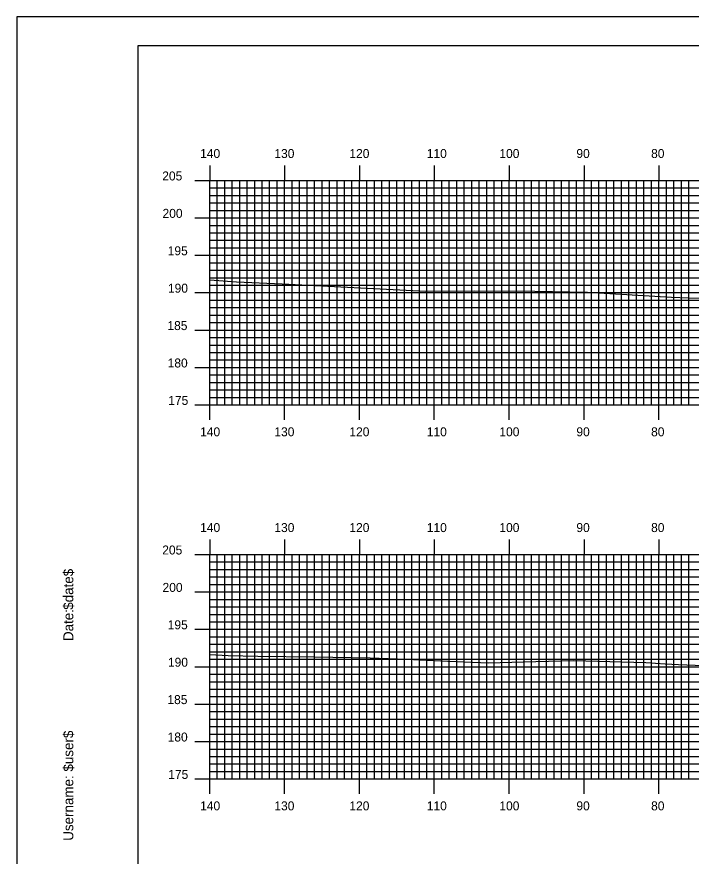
# Model space of a CAD drawing. Extents: x 1807832 to 1808175, y 442591 to 442811.
# Drawn here: x 1807832 to 1807922.1, y 442698.3 to 442810.5 of the extents above; entities that cross this region are included whole.
import ezdxf

# ---------------------------------------------------------------- set-up
doc = ezdxf.new("R2010")
doc.units = 0
for name, color, linetype in [('BORDER', 7, 'Continuous'), ('H_V ANNOTATION', 7, 'Continuous'), ('MAJOR', 7, 'Continuous'), ('MINOR', 7, 'Continuous'), ('PLOT BOUNDARY', 7, 'Continuous'), ('S_Roadway_Centerline', 7, 'Continuous')]:
    doc.layers.add(name, color=color, linetype=linetype)

msp = doc.modelspace()

# ---------------------------------------------------------------- linework, layer by layer
at = {"layer": 'BORDER'}
msp.add_lwpolyline([(1807848.18, 442596.67), (1808168.18, 442596.67), (1808168.18, 442806.67), (1807848.18, 442806.67)], close=True, dxfattribs=at)
at = {"layer": 'MAJOR'}
for p, q in [((1807857.78, 442790.67), (1807857.78, 442788.67)), ((1807867.78, 442790.67), (1807867.78, 442788.67)), ((1807877.78, 442790.67), (1807877.78, 442788.67)), ((1807887.78, 442790.67), (1807887.78, 442788.67)), ((1807897.78, 442790.67), (1807897.78, 442788.67)), ((1807907.78, 442790.67), (1807907.78, 442788.67)), ((1807917.78, 442790.67), (1807917.78, 442788.67)), ((1807855.78, 442788.67), (1807857.78, 442788.67)), ((1807857.78, 442788.67), (1808137.78, 442788.67)), ((1807857.78, 442758.67), (1807857.78, 442788.67)), ((1807857.78, 442758.67), (1807857.78, 442788.67)), ((1807857.78, 442788.67), (1808137.78, 442788.67)), ((1807867.78, 442758.67), (1807867.78, 442788.67)), ((1807877.78, 442758.67), (1807877.78, 442788.67)), ((1807887.78, 442758.67), (1807887.78, 442788.67)), ((1807897.78, 442758.67), (1807897.78, 442788.67)), ((1807907.78, 442758.67), (1807907.78, 442788.67)), ((1807917.78, 442758.67), (1807917.78, 442788.67)), ((1807855.78, 442783.67), (1807857.78, 442783.67)), ((1807857.78, 442783.67), (1808137.78, 442783.67)), ((1807855.78, 442778.67), (1807857.78, 442778.67)), ((1807857.78, 442778.67), (1808137.78, 442778.67)), ((1807855.78, 442773.67), (1807857.78, 442773.67)), ((1807857.78, 442773.67), (1808137.78, 442773.67)), ((1807855.78, 442768.67), (1807857.78, 442768.67)), ((1807857.78, 442768.67), (1808137.78, 442768.67)), ((1807855.78, 442763.67), (1807857.78, 442763.67)), ((1807857.78, 442763.67), (1808137.78, 442763.67)), ((1807855.78, 442758.67), (1807857.78, 442758.67)), ((1807857.78, 442758.67), (1808137.78, 442758.67)), ((1807857.78, 442758.67), (1808137.78, 442758.67)), ((1807857.78, 442756.66), (1807857.78, 442758.67)), ((1807867.78, 442756.66), (1807867.78, 442758.67)), ((1807877.78, 442756.66), (1807877.78, 442758.67)), ((1807887.78, 442756.66), (1807887.78, 442758.67)), ((1807897.78, 442756.66), (1807897.78, 442758.67)), ((1807907.78, 442756.66), (1807907.78, 442758.67)), ((1807917.78, 442756.66), (1807917.78, 442758.67)), ((1807857.78, 442740.67), (1807857.78, 442738.67)), ((1807867.78, 442740.67), (1807867.78, 442738.67)), ((1807877.78, 442740.67), (1807877.78, 442738.67)), ((1807887.78, 442740.67), (1807887.78, 442738.67)), ((1807897.78, 442740.67), (1807897.78, 442738.67)), ((1807907.78, 442740.67), (1807907.78, 442738.67)), ((1807917.78, 442740.67), (1807917.78, 442738.67)), ((1807855.78, 442738.67), (1807857.78, 442738.67)), ((1807857.78, 442738.67), (1808137.78, 442738.67)), ((1807857.78, 442708.67), (1807857.78, 442738.67)), ((1807857.78, 442708.67), (1807857.78, 442738.67)), ((1807857.78, 442738.67), (1808137.78, 442738.67)), ((1807867.78, 442708.67), (1807867.78, 442738.67)), ((1807877.78, 442708.67), (1807877.78, 442738.67)), ((1807887.78, 442708.67), (1807887.78, 442738.67)), ((1807897.78, 442708.67), (1807897.78, 442738.67)), ((1807907.78, 442708.67), (1807907.78, 442738.67)), ((1807917.78, 442708.67), (1807917.78, 442738.67)), ((1807855.78, 442733.67), (1807857.78, 442733.67)), ((1807857.78, 442733.67), (1808137.78, 442733.67)), ((1807855.78, 442728.67), (1807857.78, 442728.67)), ((1807857.78, 442728.67), (1808137.78, 442728.67)), ((1807855.78, 442723.67), (1807857.78, 442723.67)), ((1807857.78, 442723.67), (1808137.78, 442723.67)), ((1807855.78, 442718.67), (1807857.78, 442718.67)), ((1807857.78, 442718.67), (1808137.78, 442718.67)), ((1807855.78, 442713.67), (1807857.78, 442713.67)), ((1807857.78, 442713.67), (1808137.78, 442713.67)), ((1807855.78, 442708.67), (1807857.78, 442708.67)), ((1807857.78, 442708.67), (1808137.78, 442708.67)), ((1807857.78, 442708.67), (1808137.78, 442708.67)), ((1807857.78, 442706.66), (1807857.78, 442708.67)), ((1807867.78, 442706.66), (1807867.78, 442708.67)), ((1807877.78, 442706.66), (1807877.78, 442708.67)), ((1807887.78, 442706.66), (1807887.78, 442708.67)), ((1807897.78, 442706.66), (1807897.78, 442708.67)), ((1807907.78, 442706.66), (1807907.78, 442708.67)), ((1807917.78, 442706.66), (1807917.78, 442708.67))]:
    msp.add_line(p, q, dxfattribs=at)
at = {"layer": 'MINOR'}
for p, q in [((1807858.78, 442758.67), (1807858.78, 442788.67)), ((1807859.78, 442758.67), (1807859.78, 442788.67)), ((1807860.78, 442758.67), (1807860.78, 442788.67)), ((1807861.78, 442758.67), (1807861.78, 442788.67)), ((1807862.78, 442758.67), (1807862.78, 442788.67)), ((1807863.78, 442758.67), (1807863.78, 442788.67)), ((1807864.78, 442758.67), (1807864.78, 442788.67)), ((1807865.78, 442758.67), (1807865.78, 442788.67)), ((1807866.78, 442758.67), (1807866.78, 442788.67)), ((1807868.78, 442758.67), (1807868.78, 442788.67)), ((1807869.78, 442758.67), (1807869.78, 442788.67)), ((1807870.78, 442758.67), (1807870.78, 442788.67)), ((1807871.78, 442758.67), (1807871.78, 442788.67)), ((1807872.78, 442758.67), (1807872.78, 442788.67)), ((1807873.78, 442758.67), (1807873.78, 442788.67)), ((1807874.78, 442758.67), (1807874.78, 442788.67)), ((1807875.78, 442758.67), (1807875.78, 442788.67)), ((1807876.78, 442758.67), (1807876.78, 442788.67)), ((1807878.78, 442758.67), (1807878.78, 442788.67)), ((1807879.78, 442758.67), (1807879.78, 442788.67)), ((1807880.78, 442758.67), (1807880.78, 442788.67)), ((1807881.78, 442758.67), (1807881.78, 442788.67)), ((1807882.78, 442758.67), (1807882.78, 442788.67)), ((1807883.78, 442758.67), (1807883.78, 442788.67)), ((1807884.78, 442758.67), (1807884.78, 442788.67)), ((1807885.78, 442758.67), (1807885.78, 442788.67)), ((1807886.78, 442758.67), (1807886.78, 442788.67)), ((1807888.78, 442758.67), (1807888.78, 442788.67)), ((1807889.78, 442758.67), (1807889.78, 442788.67)), ((1807890.78, 442758.67), (1807890.78, 442788.67)), ((1807891.78, 442758.67), (1807891.78, 442788.67)), ((1807892.78, 442758.67), (1807892.78, 442788.67)), ((1807893.78, 442758.67), (1807893.78, 442788.67)), ((1807894.78, 442758.67), (1807894.78, 442788.67)), ((1807895.78, 442758.67), (1807895.78, 442788.67)), ((1807896.78, 442758.67), (1807896.78, 442788.67)), ((1807898.78, 442758.67), (1807898.78, 442788.67)), ((1807899.78, 442758.67), (1807899.78, 442788.67)), ((1807900.78, 442758.67), (1807900.78, 442788.67)), ((1807901.78, 442758.67), (1807901.78, 442788.67)), ((1807902.78, 442758.67), (1807902.78, 442788.67)), ((1807903.78, 442758.67), (1807903.78, 442788.67)), ((1807904.78, 442758.67), (1807904.78, 442788.67)), ((1807905.78, 442758.67), (1807905.78, 442788.67)), ((1807906.78, 442758.67), (1807906.78, 442788.67)), ((1807908.78, 442758.67), (1807908.78, 442788.67)), ((1807909.78, 442758.67), (1807909.78, 442788.67)), ((1807910.78, 442758.67), (1807910.78, 442788.67)), ((1807911.78, 442758.67), (1807911.78, 442788.67)), ((1807912.78, 442758.67), (1807912.78, 442788.67)), ((1807913.78, 442758.67), (1807913.78, 442788.67)), ((1807914.78, 442758.67), (1807914.78, 442788.67)), ((1807915.78, 442758.67), (1807915.78, 442788.67)), ((1807916.78, 442758.67), (1807916.78, 442788.67)), ((1807918.78, 442758.67), (1807918.78, 442788.67)), ((1807919.78, 442758.67), (1807919.78, 442788.67)), ((1807920.78, 442758.67), (1807920.78, 442788.67)), ((1807921.78, 442758.67), (1807921.78, 442788.67)), ((1807857.78, 442787.67), (1808137.78, 442787.67)), ((1807857.78, 442787.67), (1807859.79, 442787.67)), ((1807857.78, 442786.67), (1808137.78, 442786.67)), ((1807857.78, 442786.67), (1807859.79, 442786.67)), ((1807857.78, 442785.67), (1808137.78, 442785.67)), ((1807857.78, 442785.67), (1807859.79, 442785.67)), ((1807857.78, 442784.67), (1808137.78, 442784.67)), ((1807857.78, 442784.67), (1807859.79, 442784.67)), ((1807857.78, 442782.67), (1808137.78, 442782.67)), ((1807857.78, 442782.67), (1807859.79, 442782.67)), ((1807857.78, 442781.67), (1808137.78, 442781.67)), ((1807857.78, 442781.67), (1807859.79, 442781.67)), ((1807857.78, 442780.67), (1808137.78, 442780.67)), ((1807857.78, 442780.67), (1807859.79, 442780.67)), ((1807857.78, 442779.67), (1808137.78, 442779.67)), ((1807857.78, 442779.67), (1807859.79, 442779.67)), ((1807857.78, 442777.67), (1808137.78, 442777.67)), ((1807857.78, 442777.67), (1807859.79, 442777.67)), ((1807857.78, 442776.67), (1808137.78, 442776.67)), ((1807857.78, 442776.67), (1807859.79, 442776.67)), ((1807857.78, 442775.67), (1808137.78, 442775.67)), ((1807857.78, 442775.67), (1807859.79, 442775.67)), ((1807857.78, 442774.67), (1808137.78, 442774.67)), ((1807857.78, 442774.67), (1807859.79, 442774.67)), ((1807857.78, 442772.67), (1808137.78, 442772.67)), ((1807857.78, 442772.67), (1807859.79, 442772.67)), ((1807857.78, 442771.67), (1808137.78, 442771.67)), ((1807857.78, 442771.67), (1807859.79, 442771.67)), ((1807857.78, 442770.67), (1808137.78, 442770.67)), ((1807857.78, 442770.67), (1807859.79, 442770.67)), ((1807857.78, 442769.67), (1808137.78, 442769.67)), ((1807857.78, 442769.67), (1807859.79, 442769.67)), ((1807857.78, 442767.67), (1808137.78, 442767.67)), ((1807857.78, 442767.67), (1807859.79, 442767.67)), ((1807857.78, 442766.67), (1808137.78, 442766.67)), ((1807857.78, 442766.67), (1807859.79, 442766.67)), ((1807857.78, 442765.67), (1808137.78, 442765.67)), ((1807857.78, 442765.67), (1807859.79, 442765.67)), ((1807857.78, 442764.67), (1808137.78, 442764.67)), ((1807857.78, 442764.67), (1807859.79, 442764.67)), ((1807857.78, 442762.67), (1808137.78, 442762.67)), ((1807857.78, 442762.67), (1807859.79, 442762.67)), ((1807857.78, 442761.67), (1808137.78, 442761.67)), ((1807857.78, 442761.67), (1807859.79, 442761.67)), ((1807857.78, 442760.67), (1808137.78, 442760.67)), ((1807857.78, 442760.67), (1807859.79, 442760.67)), ((1807857.78, 442759.67), (1808137.78, 442759.67)), ((1807857.78, 442759.67), (1807859.79, 442759.67)), ((1807858.78, 442708.67), (1807858.78, 442738.67)), ((1807859.78, 442708.67), (1807859.78, 442738.67)), ((1807860.78, 442708.67), (1807860.78, 442738.67)), ((1807861.78, 442708.67), (1807861.78, 442738.67)), ((1807862.78, 442708.67), (1807862.78, 442738.67)), ((1807863.78, 442708.67), (1807863.78, 442738.67)), ((1807864.78, 442708.67), (1807864.78, 442738.67)), ((1807865.78, 442708.67), (1807865.78, 442738.67)), ((1807866.78, 442708.67), (1807866.78, 442738.67)), ((1807868.78, 442708.67), (1807868.78, 442738.67)), ((1807869.78, 442708.67), (1807869.78, 442738.67)), ((1807870.78, 442708.67), (1807870.78, 442738.67)), ((1807871.78, 442708.67), (1807871.78, 442738.67)), ((1807872.78, 442708.67), (1807872.78, 442738.67)), ((1807873.78, 442708.67), (1807873.78, 442738.67)), ((1807874.78, 442708.67), (1807874.78, 442738.67)), ((1807875.78, 442708.67), (1807875.78, 442738.67)), ((1807876.78, 442708.67), (1807876.78, 442738.67)), ((1807878.78, 442708.67), (1807878.78, 442738.67)), ((1807879.78, 442708.67), (1807879.78, 442738.67)), ((1807880.78, 442708.67), (1807880.78, 442738.67)), ((1807881.78, 442708.67), (1807881.78, 442738.67)), ((1807882.78, 442708.67), (1807882.78, 442738.67)), ((1807883.78, 442708.67), (1807883.78, 442738.67)), ((1807884.78, 442708.67), (1807884.78, 442738.67)), ((1807885.78, 442708.67), (1807885.78, 442738.67)), ((1807886.78, 442708.67), (1807886.78, 442738.67)), ((1807888.78, 442708.67), (1807888.78, 442738.67)), ((1807889.78, 442708.67), (1807889.78, 442738.67)), ((1807890.78, 442708.67), (1807890.78, 442738.67)), ((1807891.78, 442708.67), (1807891.78, 442738.67)), ((1807892.78, 442708.67), (1807892.78, 442738.67)), ((1807893.78, 442708.67), (1807893.78, 442738.67)), ((1807894.78, 442708.67), (1807894.78, 442738.67)), ((1807895.78, 442708.67), (1807895.78, 442738.67)), ((1807896.78, 442708.67), (1807896.78, 442738.67)), ((1807898.78, 442708.67), (1807898.78, 442738.67)), ((1807899.78, 442708.67), (1807899.78, 442738.67)), ((1807900.78, 442708.67), (1807900.78, 442738.67)), ((1807901.78, 442708.67), (1807901.78, 442738.67)), ((1807902.78, 442708.67), (1807902.78, 442738.67)), ((1807903.78, 442708.67), (1807903.78, 442738.67)), ((1807904.78, 442708.67), (1807904.78, 442738.67)), ((1807905.78, 442708.67), (1807905.78, 442738.67)), ((1807906.78, 442708.67), (1807906.78, 442738.67)), ((1807908.78, 442708.67), (1807908.78, 442738.67)), ((1807909.78, 442708.67), (1807909.78, 442738.67)), ((1807910.78, 442708.67), (1807910.78, 442738.67)), ((1807911.78, 442708.67), (1807911.78, 442738.67)), ((1807912.78, 442708.67), (1807912.78, 442738.67)), ((1807913.78, 442708.67), (1807913.78, 442738.67)), ((1807914.78, 442708.67), (1807914.78, 442738.67)), ((1807915.78, 442708.67), (1807915.78, 442738.67)), ((1807916.78, 442708.67), (1807916.78, 442738.67)), ((1807918.78, 442708.67), (1807918.78, 442738.67)), ((1807919.78, 442708.67), (1807919.78, 442738.67)), ((1807920.78, 442708.67), (1807920.78, 442738.67)), ((1807921.78, 442708.67), (1807921.78, 442738.67)), ((1807857.78, 442737.67), (1808137.78, 442737.67)), ((1807857.78, 442737.67), (1807859.79, 442737.67)), ((1807857.78, 442736.67), (1808137.78, 442736.67)), ((1807857.78, 442736.67), (1807859.79, 442736.67)), ((1807857.78, 442735.67), (1808137.78, 442735.67)), ((1807857.78, 442735.67), (1807859.79, 442735.67)), ((1807857.78, 442734.67), (1808137.78, 442734.67)), ((1807857.78, 442734.67), (1807859.79, 442734.67)), ((1807857.78, 442732.67), (1808137.78, 442732.67)), ((1807857.78, 442732.67), (1807859.79, 442732.67)), ((1807857.78, 442731.67), (1808137.78, 442731.67)), ((1807857.78, 442731.67), (1807859.79, 442731.67)), ((1807857.78, 442730.67), (1808137.78, 442730.67)), ((1807857.78, 442730.67), (1807859.79, 442730.67)), ((1807857.78, 442729.67), (1808137.78, 442729.67)), ((1807857.78, 442729.67), (1807859.79, 442729.67)), ((1807857.78, 442727.67), (1808137.78, 442727.67)), ((1807857.78, 442727.67), (1807859.79, 442727.67)), ((1807857.78, 442726.67), (1808137.78, 442726.67)), ((1807857.78, 442726.67), (1807859.79, 442726.67)), ((1807857.78, 442725.67), (1808137.78, 442725.67)), ((1807857.78, 442725.67), (1807859.79, 442725.67)), ((1807857.78, 442724.67), (1808137.78, 442724.67)), ((1807857.78, 442724.67), (1807859.79, 442724.67)), ((1807857.78, 442722.67), (1808137.78, 442722.67)), ((1807857.78, 442722.67), (1807859.79, 442722.67)), ((1807857.78, 442721.67), (1808137.78, 442721.67)), ((1807857.78, 442721.67), (1807859.79, 442721.67)), ((1807857.78, 442720.67), (1808137.78, 442720.67)), ((1807857.78, 442720.67), (1807859.79, 442720.67)), ((1807857.78, 442719.67), (1808137.78, 442719.67)), ((1807857.78, 442719.67), (1807859.79, 442719.67)), ((1807857.78, 442717.67), (1808137.78, 442717.67)), ((1807857.78, 442717.67), (1807859.79, 442717.67)), ((1807857.78, 442716.67), (1808137.78, 442716.67)), ((1807857.78, 442716.67), (1807859.79, 442716.67)), ((1807857.78, 442715.67), (1808137.78, 442715.67)), ((1807857.78, 442715.67), (1807859.79, 442715.67)), ((1807857.78, 442714.67), (1808137.78, 442714.67)), ((1807857.78, 442714.67), (1807859.79, 442714.67)), ((1807857.78, 442712.67), (1808137.78, 442712.67)), ((1807857.78, 442712.67), (1807859.79, 442712.67)), ((1807857.78, 442711.67), (1808137.78, 442711.67)), ((1807857.78, 442711.67), (1807859.79, 442711.67)), ((1807857.78, 442710.67), (1808137.78, 442710.67)), ((1807857.78, 442710.67), (1807859.79, 442710.67)), ((1807857.78, 442709.67), (1808137.78, 442709.67)), ((1807857.78, 442709.67), (1807859.79, 442709.67))]:
    msp.add_line(p, q, dxfattribs=at)
at = {"layer": 'PLOT BOUNDARY'}
msp.add_lwpolyline([(1807832, 442590.55), (1808172, 442590.55), (1808172, 442810.55), (1807832, 442810.55)], close=True, dxfattribs=at)
at = {"layer": 'S_Roadway_Centerline'}
for points in [[(1807857.78, 442775.39), (1807861.36, 442775.12), (1807867.43, 442774.86), (1807886.65, 442773.87), (1807893.13, 442773.93), (1807901.22, 442773.85), (1807908.23, 442773.74), (1807919.48, 442773.06), (1807921.73, 442772.99), (1807936.94, 442772.83)], [(1807857.78, 442725.32), (1807860.24, 442725.15), (1807864.2, 442725.07), (1807871.73, 442724.98), (1807879.22, 442724.86), (1807884.05, 442724.66), (1807889.58, 442724.42), (1807895.08, 442724.17), (1807899.67, 442724.31), (1807906.44, 442724.51), (1807916.02, 442724.23), (1807918.61, 442724.06), (1807920.41, 442723.96), (1807940.51, 442723.16)]]:
    msp.add_lwpolyline(points, dxfattribs=at)

# ---------------------------------------------------------------- texts
at = {"layer": 'BORDER'}
for s, p in [('$date$', (1807839.55, 442731.28)), ('Date:', (1807839.55, 442727.1)), ('$user$', (1807839.55, 442709.65)), ('Username:', (1807839.55, 442700.4))]:
    msp.add_text(s, height=1.339, rotation=90, dxfattribs=at).set_placement(p)
at = {"layer": 'H_V ANNOTATION'}
for s, p in [('140', (1807856.49, 442791.67)), ('130', (1807866.41, 442791.67)), ('120', (1807876.43, 442791.67)), ('110', (1807886.77, 442791.67)), ('100', (1807896.47, 442791.67)), ('90', (1807906.76, 442791.67)), ('80', (1807916.74, 442791.67)), ('205', (1807851.43, 442788.67)), ('200', (1807851.47, 442783.67)), ('195', (1807852.16, 442778.67)), ('190', (1807852.19, 442773.67)), ('185', (1807852.12, 442768.67)), ('180', (1807852.15, 442763.67)), ('175', (1807852.23, 442758.67)), ('140', (1807856.49, 442754.47)), ('130', (1807866.41, 442754.47)), ('120', (1807876.43, 442754.47)), ('110', (1807886.77, 442754.47)), ('100', (1807896.47, 442754.47)), ('90', (1807906.76, 442754.47)), ('80', (1807916.74, 442754.47)), ('140', (1807856.49, 442741.67)), ('130', (1807866.41, 442741.67)), ('120', (1807876.43, 442741.67)), ('110', (1807886.77, 442741.67)), ('100', (1807896.47, 442741.67)), ('90', (1807906.76, 442741.67)), ('80', (1807916.74, 442741.67)), ('205', (1807851.43, 442738.67)), ('200', (1807851.47, 442733.67)), ('195', (1807852.16, 442728.67)), ('190', (1807852.19, 442723.67)), ('185', (1807852.12, 442718.67)), ('180', (1807852.15, 442713.67)), ('175', (1807852.23, 442708.67)), ('140', (1807856.49, 442704.47)), ('130', (1807866.41, 442704.47)), ('120', (1807876.43, 442704.47)), ('110', (1807886.77, 442704.47)), ('100', (1807896.47, 442704.47)), ('90', (1807906.76, 442704.47)), ('80', (1807916.74, 442704.47))]:
    msp.add_text(s, height=1.2, dxfattribs=at).set_placement(p)
at = {"layer": 'MAJOR'}
for p in [(1807857.78, 442758.67), (1807857.78, 442708.67)]:
    msp.add_text('-', height=0.012, dxfattribs=at).set_placement(p)

doc.saveas('drawing.dxf')
